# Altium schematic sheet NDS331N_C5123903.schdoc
size 127 x 101 mm
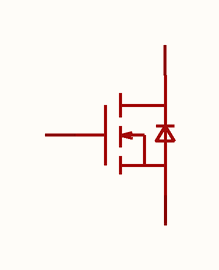
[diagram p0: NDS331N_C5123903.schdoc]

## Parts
Q?  nds331n  [SOT-23-3_L2.9-W1.5-P1.90-LS2.6-BR]  (value not drawn)

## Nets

Not connected (* = marked no-connect by the designer): Q? 1(G) 2(S) 3(D)

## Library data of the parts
Q? = nds331n: 漏源电压(Vdss):20V;连续漏极电流(Id):5.5A;导通电阻(RDS(on)):25mΩ@4.5V,4A;耗散功率(Pd):1W;阈值电压(Vgs(th)):1V;; Manufacturer: TECH PUBLIC(台舟); Symbol: NDS331N_C5123903; AddInBom: yes; ModelId: 10336ff038a745ff8e8286e7fc8d5503; ModelTransform: 114.173,102.362,0,90,0,0,0,0,0; Drain to Source Voltage: 20V; Current - Continuous Drain(Id): 5.5A; Pd - Power Dissipation: 1W; Gate Threshold Voltage (Vgs(th)@Id): 1V; Gate Charge(Qg): 4nC@10V; Input Capacitance(Ciss@Vds): 300pF; Reverse Transfer Capacitance (Crss@Vds): 80pF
